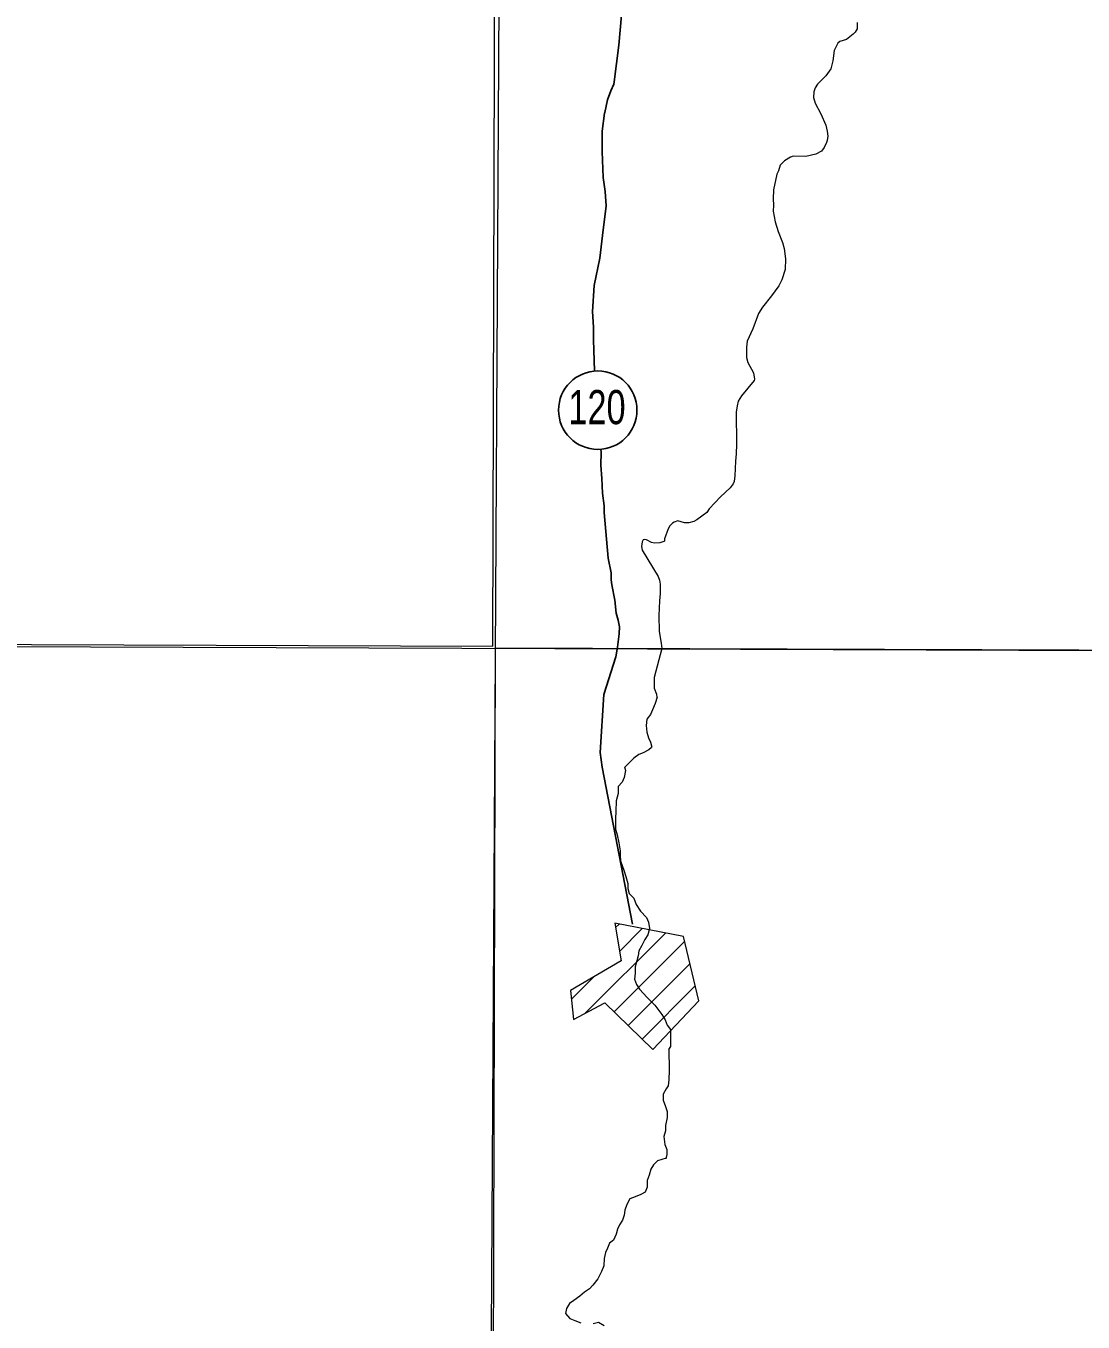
# Model space of a CAD drawing. Extents: x -1643653 to 4543381, y 1624270 to 13878484.
# Drawn here: x 606613 to 608778, y 8908511 to 8911165 of the extents above; entities that cross this region are included whole.
import ezdxf
from ezdxf.enums import TextEntityAlignment as Align

# ---------------------------------------------------------------- set-up
doc = ezdxf.new("R2010")
doc.units = 0
doc.header["$LTSCALE"] = 200
doc.layers.add('1', color=7, linetype='Continuous', lineweight=13)
doc.layers.add('6', color=7, linetype='Continuous', lineweight=13)

msp = doc.modelspace()

# ---------------------------------------------------------------- linework, layer by layer
at = {"layer": '1', "lineweight": 25}
msp.add_spline([(814781, 9009175.5), (814787.2, 9009173.4), (814796.9, 9009173.4), (814799.4, 9009172.4), (814805.1, 9009174.5), (814805.6, 9009176.5), (814811.7, 9009179.5), (814811.7, 9009179.5), (814801.5, 9009181), (814790.7, 9009181.5), (814784.1, 9009183.1), (814777.4, 9009185.1), (814778.4, 9009175.5)], degree=3, dxfattribs=at)
at = {"layer": '6'}
for p, q in [((574653.9, 8910009.3), (626625.7, 8909822.1)), ((607820.8, 8909318.7), (607828.1, 8909326)), ((607758.6, 8909143.3), (607922.8, 8909307.5)), ((607828.8, 8909270.1), (607875.4, 8909316.8)), ((607817.9, 8909146.1), (607962.5, 8909290.7)), ((607846.6, 8909118.2), (607973.3, 8909244.9)), ((607730.5, 8909171.9), (607776.5, 8909217.8)), ((607875.3, 8909090.3), (607984.2, 8909199.2))]:
    msp.add_line(p, q, dxfattribs=at)
for points in [[(607657.7, 8924743.3), (607574.2, 8909874.9), (607492.3, 8896026.7)], [(608315.5, 8911171.7), (608315.6, 8911158.5), (608311.6, 8911151.9), (608307.3, 8911147.5), (608293.6, 8911136.9), (608280, 8911133), (608275.9, 8911129.4), (608268.8, 8911114.5), (608265.9, 8911093.2), (608261.9, 8911077.1), (608251.5, 8911062.7), (608234.4, 8911045.7), (608229.6, 8911037.8), (608226.7, 8911030.1), (608226, 8911018.3), (608229.5, 8911006.7), (608241.4, 8910985), (608251.6, 8910961.2), (608254.2, 8910949.4), (608255.3, 8910939.2), (608254.1, 8910930.4), (608252.7, 8910925.9), (608247.8, 8910915.8), (608242.3, 8910908.2), (608231, 8910902.2), (608210.4, 8910897.2), (608184.7, 8910897.9), (608178.9, 8910895.7), (608167, 8910888.8), (608158.1, 8910879.6), (608154.4, 8910868.3), (608151.1, 8910860.9), (608144.3, 8910828.8), (608143.3, 8910810.6), (608144.4, 8910798), (608143.9, 8910785.4), (608147.5, 8910763.3), (608153.7, 8910743.5), (608162.5, 8910721.4), (608166.3, 8910708.8), (608168.7, 8910688.2), (608168.3, 8910666.1), (608161.6, 8910644.7), (608155.1, 8910632.9), (608140.4, 8910611.9), (608121.6, 8910588.8), (608113.6, 8910576.1), (608102.1, 8910544.4), (608090.7, 8910519.2), (608088.7, 8910506.7), (608089.2, 8910486.1), (608091.9, 8910475.9), (608103.1, 8910454.4), (608105.7, 8910441.4), (608104.8, 8910439.1), (608078.6, 8910407.5), (608072, 8910396.6)], [(608072, 8910396.6), (608069.6, 8910387.1), (608068.1, 8910373.8), (608068.3, 8910308.2), (608067.6, 8910288.4), (608066.2, 8910273.5), (608065.1, 8910243.4), (608063.5, 8910232.3), (608061.9, 8910227), (608055.7, 8910219), (608035.7, 8910200.6), (608012.5, 8910176.3), (608007.7, 8910168.6), (607987.3, 8910153.6), (607980.8, 8910149.9), (607970.7, 8910147.2), (607961.9, 8910147.3), (607948.5, 8910151.3), (607941.1, 8910148.7), (607937.3, 8910146.5), (607932.1, 8910141.4), (607928.5, 8910134.9), (607921.3, 8910114.9), (607920.8, 8910110.1), (607919.9, 8910108.9), (607911.6, 8910106.4), (607900.5, 8910105.6), (607894.4, 8910107.2), (607884.3, 8910112.4), (607879.3, 8910113.2), (607877.1, 8910112.3), (607875.3, 8910108.4), (607873.8, 8910098.7), (607875, 8910091.5), (607907.8, 8910037.4), (607910.9, 8910030.1), (607911.9, 8910021.7)], [(607911.9, 8910021.7), (607911.9, 8910002.7), (607911.9, 8910002.7), (607910.6, 8909987.8), (607909.5, 8909957.7), (607910.2, 8909924.6), (607914.4, 8909900.9), (607915.5, 8909889.9), (607900.2, 8909830.5)], [(607900.2, 8909830.5), (607900.1, 8909819.3), (607900, 8909809.1), (607905, 8909796.9), (607905.6, 8909789.5)], [(607905.8, 8909790.3), (607901.8, 8909777.5), (607896.7, 8909764.3), (607892.5, 8909755.2), (607884.8, 8909745.4), (607883.4, 8909732.4), (607884.8, 8909718.5), (607888.1, 8909707.3), (607892.1, 8909698.2), (607894.9, 8909687.9)], [(607894.5, 8909687.5), (607889, 8909682.9), (607877.7, 8909676.8), (607868.6, 8909672.8), (607858.3, 8909665.8), (607851.2, 8909658.7), (607839.5, 8909647.1)], [(607839.2, 8909647.8), (607841.5, 8909640), (607838.4, 8909625.7), (607834.3, 8909616.6), (607826.1, 8909607.5), (607826, 8909593.2), (607821.8, 8909578), (607821.6, 8909556.6), (607820.5, 8909542.3), (607820.5, 8909532.2), (607820.4, 8909519.9), (607824.3, 8909508.7), (607827.3, 8909492.4), (607830.2, 8909476.1), (607830.2, 8909465.9), (607831.1, 8909455.7), (607834.1, 8909445.5), (607838.1, 8909436.3), (607842.1, 8909423), (607846, 8909408.8), (607846, 8909398.6), (607849, 8909388.4), (607858, 8909379.2), (607863, 8909365.9), (607872.1, 8909352.6), (607884.2, 8909339.3), (607888.2, 8909330.1), (607890.2, 8909316.8), (607887, 8909303.6), (607880.8, 8909294.5), (607874.7, 8909282.3), (607868.5, 8909271.1), (607867.4, 8909260.9), (607864.3, 8909250.8), (607861.1, 8909238.6), (607861.1, 8909225.3), (607859.9, 8909213.1), (607863.9, 8909201.9), (607870, 8909192.7), (607878.1, 8909183.5), (607885.1, 8909176.3), (607893.2, 8909168.1), (607901.3, 8909159.9), (607909.3, 8909148.7), (607915.4, 8909140.5)], [(607915.4, 8909140.5), (607922.4, 8909130.2), (607926.4, 8909119), (607933.5, 8909109.8), (607933.4, 8909097.6), (607933.3, 8909086.4), (607933.2, 8909075.2), (607929.2, 8909068.9)], [(607928.5, 8908994.8), (607924.7, 8908988.9), (607918.5, 8908977.7), (607918.4, 8908965.5), (607923.4, 8908952.2), (607926.4, 8908942), (607926.3, 8908929.8), (607923.2, 8908913.5), (607923.1, 8908902.3), (607920, 8908891.2), (607921.9, 8908874.8), (607925.9, 8908864.6), (607925.8, 8908854.4), (607923.9, 8908845.1)], [(607924.2, 8908846.6), (607906.4, 8908841.3), (607898.2, 8908833.2), (607893, 8908824.1), (607889.9, 8908811.9), (607885.8, 8908800.7), (607885.7, 8908787.5), (607881.5, 8908777.3), (607872.3, 8908772.3), (607861.1, 8908767.2), (607849.9, 8908763.2), (607843.7, 8908752.1), (607839.6, 8908739.9), (607838.5, 8908729.7), (607835.3, 8908719.5), (607829.2, 8908710.4), (607825.1, 8908701.3), (607821.9, 8908691.1), (607816.8, 8908678.9), (607808.6, 8908672.9), (607804.4, 8908662.7), (607800.3, 8908653.6), (607797.2, 8908641.3), (607797.1, 8908626.1), (607791.9, 8908614.9), (607784.7, 8908599.7), (607774.4, 8908586.5), (607767.2, 8908579.4), (607757, 8908572.3), (607747.8, 8908564.2), (607735.5, 8908555.2), (607726.3, 8908549.1), (607720.2, 8908539), (607718.1, 8908528.8), (607727.2, 8908518.6), (607737.3, 8908514.4), (607749.5, 8908509.2)], [(607774.9, 8908508.1), (607786.1, 8908511.1), (607797.2, 8908503.9)]]:
    msp.add_lwpolyline(points, dxfattribs=at)
for points in [[(607600.8, 8920952.4), (596639.8, 8920989.8), (596608.8, 8909934.4), (607569.8, 8909894.9)], [(618535.2, 8909853.3), (607574.3, 8909890.7), (607543.3, 8898835.3), (618504.2, 8898795.8)], [(607819.3, 8909327.7), (607832, 8909250.5), (607728.8, 8909189.8), (607734.5, 8909130.7), (607798.9, 8909164.5), (607897.1, 8909069.2), (607991.4, 8909168.6), (607960.2, 8909300.2)]]:
    msp.add_lwpolyline(points, close=True, dxfattribs=at)
at = {"layer": '6', "lineweight": 25}
for points in [[(607784.9, 8911999.6), (607782.1, 8911967.5), (607781.3, 8911929.5), (607788, 8911886.9), (607792.5, 8911839.5), (607788.3, 8911760.4), (607788.9, 8911720.9), (607793.1, 8911695.9), (607802, 8911666.8), (607810.5, 8911630.6), (607820.1, 8911605.6), (607832.4, 8911579), (607837.3, 8911566.1), (607839.5, 8911553.2), (607843.7, 8911515.3), (607845.8, 8911475.8), (607845.1, 8911393), (607845.4, 8911323.6), (607839.9, 8911277.2), (607839.1, 8911261.7), (607839.2, 8911246.2), (607835.7, 8911217.9), (607827.2, 8911125.4)], [(607827.2, 8911125.4), (607818.3, 8911050.1), (607817.3, 8911045.7), (607811.1, 8911032.1), (607804.2, 8911013.7), (607798.7, 8910987.7)], [(607798.7, 8910987.7), (607798.4, 8910986.3), (607793.6, 8910949.1), (607793.1, 8910907.6), (607795.5, 8910854.2), (607799.3, 8910825.8), (607801.4, 8910796.7), (607794, 8910735.7)], [(607794, 8910735.7), (607788.4, 8910689.2), (607776.8, 8910633.3), (607773.3, 8910579.9), (607775.9, 8910548.2), (607775.9, 8910522), (607777.9, 8910458.8)], [(607790.9, 8910298.5), (607791.2, 8910292), (607790.9, 8910265.3), (607792.9, 8910237.8), (607794, 8910207.8), (607797.2, 8910181.9), (607797.8, 8910168.2), (607805.9, 8910075.3), (607811.7, 8910045.2), (607812, 8910030.6), (607813.2, 8910020.3), (607819.2, 8909989.3), (607822.2, 8909962.7), (607826.4, 8909948.1), (607828.6, 8909934.3), (607828.1, 8909919.8), (607824.7, 8909893.1), (607821.4, 8909873.3)], [(607821.4, 8909873.3), (607797, 8909796.1), (607789.4, 8909676.9), (607793.4, 8909647.3), (607855.8, 8909325.6)]]:
    msp.add_lwpolyline(points, dxfattribs=at)
msp.add_circle((607784.4, 8910378), 80.3, dxfattribs=at)
at = {"layer": '6'}
msp.add_spline([(607929.6, 8909069.6), (607930.5, 8909038.8), (607930.5, 8909019.9), (607928.3, 8908994.5)], degree=3, dxfattribs=at)

# ---------------------------------------------------------------- texts
at = {"layer": '6', "width": 0.75}
msp.add_text('120', height=70, dxfattribs=at).set_placement((607782.8, 8910349.3), align=Align.CENTER)

doc.saveas('drawing.dxf')
